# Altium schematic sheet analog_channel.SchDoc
size A4; SheetNumber: 3; SheetTotal: 5
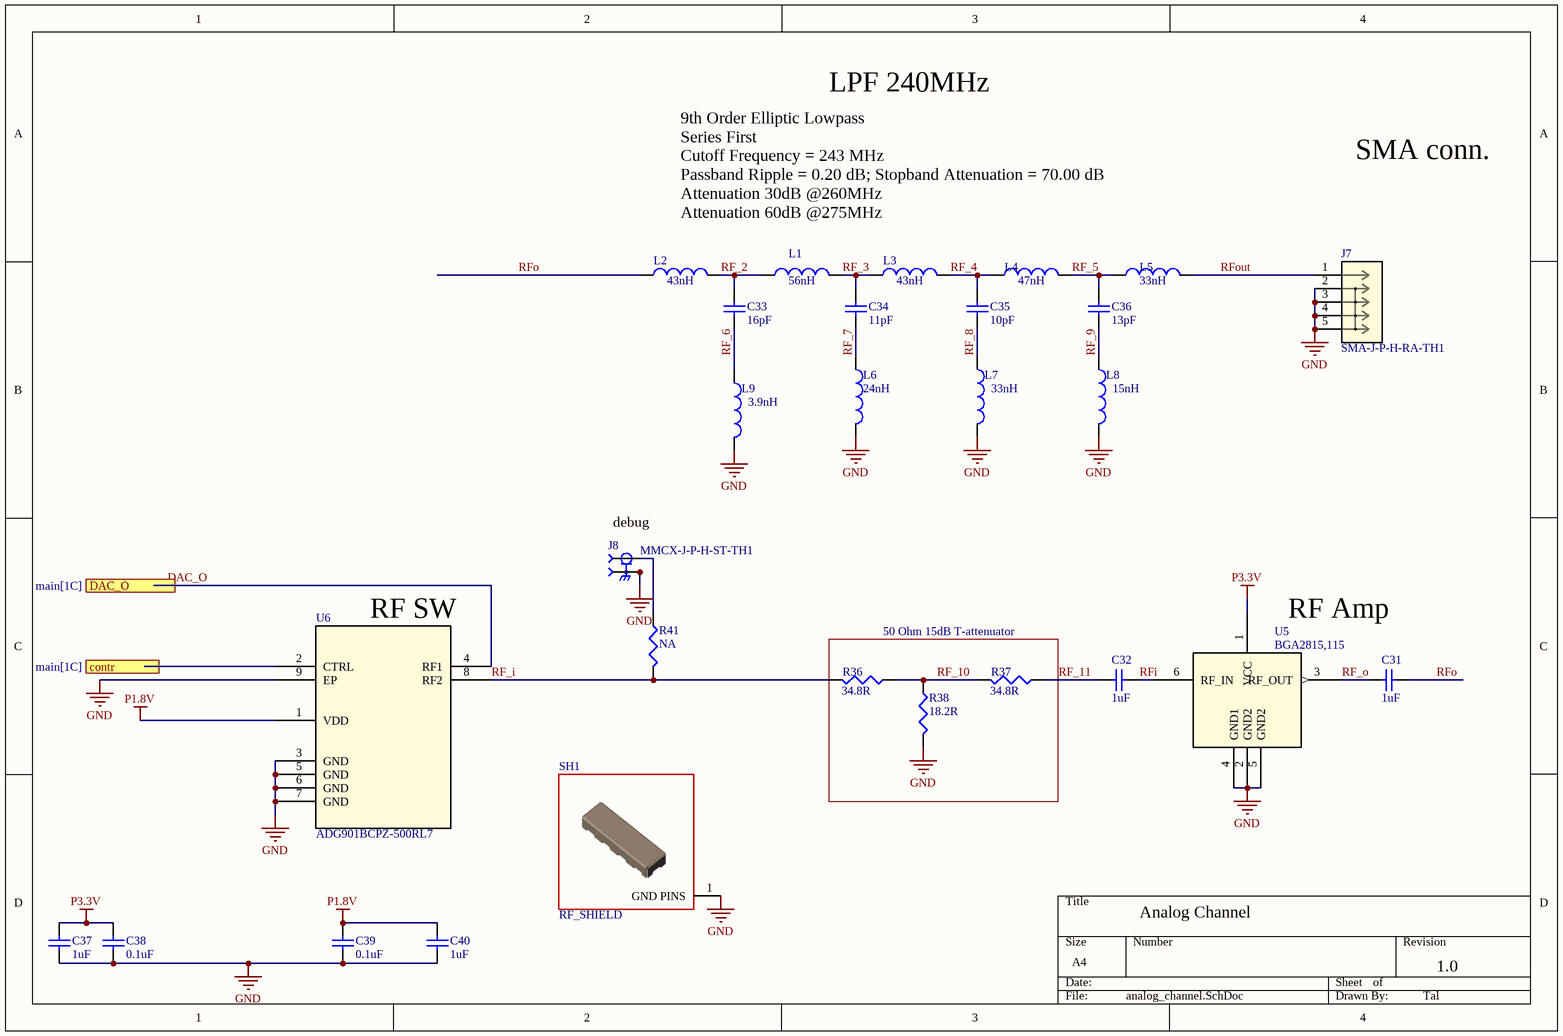
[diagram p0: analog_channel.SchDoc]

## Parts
C31  Capacitance: 1uF  [C0402]  (hidden comment: 1uF 25V)
C32  Capacitance: 1uF  [C0402]  (hidden comment: 1uF 25V)
C33  Capacitance: 16pF  [C0402]  (hidden comment: 16pF 50V)
C34  Capacitance: 11pF  [C0402]  (hidden comment: 11pF 50V)
C35  Capacitance: 10pF  [C0402]  (hidden comment: 10pF 50V)
C36  Capacitance: 13pF  [C0402]  (hidden comment: 13pF 50V)
C37  Capacitance: 1uF  [C0402]  (hidden comment: 1uF 25V)
C38  Capacitance: 0.1uF  [C0402]  (hidden comment: 0.1uF 50V)
C39  Capacitance: 0.1uF  [C0402]  (hidden comment: 0.1uF 50V)
C40  Capacitance: 1uF  [C0402]  (hidden comment: 1uF 25V)
J7  SMA-J-P-H-RA-TH1  [CONN_SMA-J-P-H-RA-TH1_SAI]
J8  MMCX-J-P-H-ST-TH1  [SAMTEC_MMCX-J-P-H-ST-TH1]
L1  value 56nH  [0402-A]  (hidden comment: Inductor)
L2  value 43nH  [0402-A]  (hidden comment: Inductor)
L3  value 43nH  [0402-A]  (hidden comment: Inductor)
L4  value 47nH  [0402-A]  (hidden comment: Inductor)
L5  value 33nH  [0402-A]  (hidden comment: Inductor)
L6  value 24nH  [0402-A]  (hidden comment: Inductor)
L7  value 33nH  [0402-A]  (hidden comment: Inductor)
L8  value 15nH  [0402-A]  (hidden comment: Inductor)
L9  value 3.9nH  [0402-A]  (hidden comment: Inductor)
R36  34.8R  [r0402]
R37  34.8R  [r0402]
R38  18.2R  [r0402]
R41  NA  [r0402]
SH1  RF_SHIELD  [RF_Sh]
U5  BGA2815,115  [SOT_2815,115_NXP]
U6  ADG901BCPZ-500RL7  [CP_8_2_ADI]

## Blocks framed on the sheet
50 Ohm 15dB T-attenuator: R36-R38

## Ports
contr (in, see main[1C]), DAC_O (in, see main[1C])

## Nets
GND: C37.1 C38.1 C39.1 C40.1 J7.2 J7.3 J7.4 J7.5 J8.S1 J8.S2 J8.S3 J8.S4 L6.2 L7.2 L8.2 L9.2 R38.2 SH1.1(GND_PINS) U5.2(GND2) U5.4(GND1) U5.5(GND2) U6.3(GND) U6.5(GND) U6.6(GND) U6.7(GND) U6.9(EP)
P1.8V: C39.2 C40.2 U6.1(VDD)
P3.3V: C37.2 C38.2 U5.1(VCC)
contr: U6.2(CTRL) ; port contr
DAC_O: U6.4(RF1) ; port DAC_O
RF_2: C33.1 L1.1 L2.2
RF_3: C34.1 L1.2 L3.1
RF_4: C35.1 L3.2 L4.1
RF_5: C36.1 L4.2 L5.1
RF_6: C33.2 L9.1
RF_7: C34.2 L6.1
RF_8: C35.2 L7.1
RF_9: C36.2 L8.1
RF_10: R36.1 R37.2 R38.1
RF_11: C32.1 R37.1
RF_i: R36.2 R41.2 U6.8(RF2)
RF_o: C31.1 U5.3(RF_OUT)
RFi: C32.2 U5.6(RF_IN)
RFo: C31.2 L2.1
RFout: J7.1 L5.2
NetJ8_1: J8.1 R41.1

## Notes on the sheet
- LPF 240MHz
- SMA conn.
- 9th Order Elliptic Lowpass
  Series First
  Cutoff Frequency = 243 MHz
  Passband Ripple = 0.20 dB; Stopband Attenuation = 70.00 dB
  Attenuation 30dB @260MHz
  Attenuation 60dB @275MHz
- (near J8) debug
- (near U6) RF SW
- (near U5) RF Amp
- Analog Channel
- 1.0
- Tal

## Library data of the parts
C31 C32 C37 C40 = CAP CER 6.8pF 50V NP0 0402: CAP CER 1uF 25V X5R 0402; Manufacturer Part Number: C1005C0G1H6R8D; Manufacturer: TDK Corporation; LANDA P/N: ECP-000033; Voltage - Rated: 50V
C33 = CAP CER 20pF 50V 5% NP0 0402: CAP CER 16PF 50V 5% NP0 0402; Manufacturer: TDK Corporation; Manufacturer Part Number: C1005C0G1H200J; LANDA P/N: ECP-000034
C34 = CAP CER 20pF 50V 5% NP0 0402: CAP CER 11PF 50V 5% NP0 0402; Manufacturer: TDK Corporation; Manufacturer Part Number: C1005C0G1H200J; LANDA P/N: ECP-000034
C35 = CAP CER 20pF 50V 5% NP0 0402: CAP CER 10PF 50V 5% NP0 0402; Manufacturer: TDK Corporation; Manufacturer Part Number: C1005C0G1H200J; LANDA P/N: ECP-000034
C36 = CAP CER 20pF 50V 5% NP0 0402: CAP CER 13PF 50V 5% NP0 0402; Manufacturer: TDK Corporation; Manufacturer Part Number: C1005C0G1H200J; LANDA P/N: ECP-000034
C38 C39 = CAP CER 6.8pF 50V NP0 0402: CAP CER 0.1uF 50V NP0 0402; Manufacturer Part Number: C1005C0G1H6R8D; Manufacturer: TDK Corporation; LANDA P/N: ECP-000033
J7 = SMA-J-P-H-RA-TH1: No Description Available; Mfr_Name: Samtec Inc
J8 = MMCX-J-P-H-ST-TH1: MMCX STRAIGHT, THROUGH HOLE JACK- 50 OHM; MF: Samtec
L1-L9 = Inductor: Code_IEC: 1005
R36 R37 = RES 100 OHM 1/10W 1% 0402 SMD: RES 34.8 OHM 1/10W 1% 0402 SMD; Manufacturer Part Number: ERJ-2RKF1000X; Manufacturer: Panasonic Electronic Components; LANDA P/N: ERS-000079; Assembly: N.C
R38 = RES 100 OHM 1/10W 1% 0402 SMD: RES 18.2 OHM 1/10W 1% 0402 SMD; Manufacturer Part Number: ERJ-2RKF1000X; Manufacturer: Panasonic Electronic Components; LANDA P/N: ERS-000079; Assembly: N.C
R41 = RES 100 OHM 1/10W 1% 0402 SMD: RES 0 OHM 1/10W 1% 0402 SMD; Manufacturer Part Number: ERJ-2RKF1000X; Manufacturer: Panasonic Electronic Components; LANDA P/N: ERS-000079; Assembly: N.C
SH1 = RF_SHIELD_1: RF Shield Cover 0.300" (7.62mm) X 1.000" (25.40mm) Non-Vented Surface Mount; Manufacturer_Part_Number: G-0300SB1000-0100XC; Manufacturer: Orbel Corporation
U5 = BGA2815,115: No Description Available; Mfr_Name: NXP
U6 = ADG901BCPZ-500RL7: No Description Available; Mfr_Name: Analog Devices Inc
